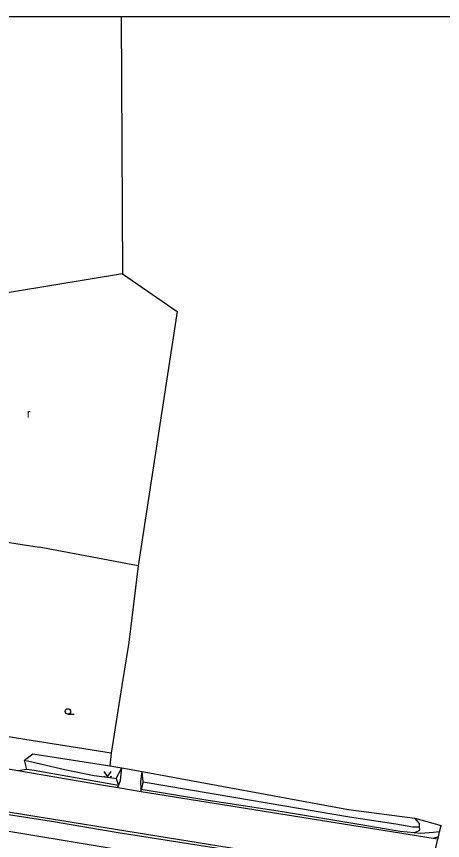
# Model space of a CAD drawing. Extents: x -591353 to -591106, y -1167325 to -1167155.
# Drawn here: x -591295 to -591237.1, y -1167266.9 to -1167154.8 of the extents above; entities that cross this region are included whole.
import ezdxf

# ---------------------------------------------------------------- set-up
doc = ezdxf.new("R2010")
doc.units = 0
for name, color, linetype in [('Level 36', 7, 'Continuous'), ('Vrstva 10', 7, 'Continuous'), ('Vrstva 11', 7, 'Continuous'), ('Vrstva 51', 7, 'Continuous'), ('Vrstva 63', 7, 'Continuous'), ('Vrstva 7', 7, 'Continuous')]:
    doc.layers.add(name, color=color, linetype=linetype)

msp = doc.modelspace()

# ---------------------------------------------------------------- linework, layer by layer
at = {"layer": 'Level 36'}
msp.add_line((-591288.05, -1167249.75), (-591287.18, -1167249.75), dxfattribs=at)
msp.add_lwpolyline([(-591283.14, -1167257.54), (-591282.64, -1167258.29), (-591282.14, -1167257.54)], dxfattribs=at)
for centre, radius in [((-591288.05, -1167249.37), 0.375), ((-591283.09, -1167258.24), 0.05), ((-591282.19, -1167258.24), 0.05)]:
    msp.add_circle(centre, radius, dxfattribs=at)
at = {"layer": 'Vrstva 10'}
for points in [[(-591294.86, -1167257.43), (-591297.72, -1167256.94)], [(-591281.26, -1167259.76), (-591282.92, -1167259.49), (-591294.86, -1167257.43)], [(-591315.62, -1167259.92), (-591254.87, -1167269.68), (-591254.39, -1167269.76), (-591239.02, -1167272.22)], [(-591278.06, -1167260.29), (-591281.26, -1167259.76)], [(-591238.35, -1167266.67), (-591278.06, -1167260.29)], [(-591237.71, -1167266.77), (-591238.35, -1167266.67)]]:
    msp.add_lwpolyline(points, dxfattribs=at)
at = {"layer": 'Vrstva 11'}
for points in [[(-591293.95, -1167255.98), (-591292.82, -1167255.12)], [(-591292.82, -1167255.12), (-591282.36, -1167256.75)], [(-591282.18, -1167255.04), (-591282.36, -1167256.75)], [(-591293.62, -1167257.29), (-591293.95, -1167255.98)], [(-591293.95, -1167255.98), (-591293.54, -1167256.08), (-591291.76, -1167256.52), (-591288.27, -1167257.3), (-591284.47, -1167258.07), (-591281.69, -1167258.44), (-591281.48, -1167258.49)], [(-591293.62, -1167257.29), (-591294.86, -1167257.43)], [(-591281.17, -1167259.46), (-591285.5, -1167258.69), (-591292.62, -1167257.41), (-591293.62, -1167257.29)], [(-591282.36, -1167256.75), (-591280.69, -1167257.06)], [(-591281.48, -1167258.49), (-591280.69, -1167257.06)], [(-591281.17, -1167259.46), (-591280.91, -1167258.78), (-591280.69, -1167257.06)], [(-591280.69, -1167257.06), (-591277.93, -1167257.56)], [(-591278.09, -1167259.97), (-591278.11, -1167258.89), (-591277.93, -1167257.56)], [(-591277.8, -1167258.94), (-591277.93, -1167257.56)], [(-591277.93, -1167257.56), (-591249.87, -1167262.71), (-591240.85, -1167263.9)], [(-591281.48, -1167258.49), (-591281.17, -1167259.46)], [(-591277.8, -1167258.94), (-591278.09, -1167259.97)], [(-591277.8, -1167258.94), (-591265.45, -1167261.03), (-591249.75, -1167263.69), (-591243.42, -1167264.68), (-591241.1, -1167265.05), (-591240.19, -1167265.08)], [(-591281.26, -1167259.76), (-591281.17, -1167259.46)], [(-591278.06, -1167260.29), (-591278.09, -1167259.97)], [(-591240.93, -1167265.89), (-591242.85, -1167265.7), (-591248.46, -1167264.77), (-591258.86, -1167263.05), (-591269.56, -1167261.38), (-591278.09, -1167259.97)], [(-591239.14, -1167272.71), (-591240.68, -1167272.27), (-591248.29, -1167271.11), (-591264.99, -1167268.44), (-591281.22, -1167265.9), (-591290.29, -1167264.35), (-591306.42, -1167261.83), (-591315.71, -1167260.43)], [(-591316.07, -1167262.37), (-591254.81, -1167272.53), (-591239.7, -1167275.04)], [(-591240.85, -1167263.9), (-591237.26, -1167264.89)], [(-591240.19, -1167265.08), (-591240.22, -1167264.61), (-591240.85, -1167263.9)], [(-591240.93, -1167265.89), (-591240.17, -1167265.54), (-591240.19, -1167265.08)], [(-591237.47, -1167265.76), (-591237.26, -1167264.89)], [(-591237.47, -1167265.76), (-591238.28, -1167265.86), (-591240.05, -1167265.97), (-591240.93, -1167265.89)], [(-591239.02, -1167272.22), (-591237.71, -1167266.77)], [(-591237.63, -1167266.45), (-591238.35, -1167266.67)], [(-591237.71, -1167266.77), (-591237.63, -1167266.45)], [(-591237.63, -1167266.45), (-591237.47, -1167265.76)]]:
    msp.add_lwpolyline(points, dxfattribs=at)
at = {"layer": 'Vrstva 51'}
msp.add_line((-591280.82, -1167154.81), (-591280.64, -1167189.82), dxfattribs=at)
for points in [[(-591280.64, -1167189.82), (-591310.05, -1167194.7)], [(-591280.64, -1167189.82), (-591273.17, -1167194.95)], [(-591273.17, -1167194.95), (-591278.51, -1167229.54)], [(-591296.6, -1167226.29), (-591291.94, -1167227.04)], [(-591278.51, -1167229.54), (-591291.94, -1167227.04)]]:
    msp.add_lwpolyline(points, dxfattribs=at)
at = {"layer": 'Vrstva 63'}
msp.add_lwpolyline([(-591352.57, -1167154.81), (-591106.03, -1167154.81), (-591106.03, -1167325.38), (-591352.57, -1167325.38)], close=True, dxfattribs=at)
at = {"layer": 'Vrstva 7'}
for points in [[(-591278.51, -1167229.54), (-591279.78, -1167240), (-591280.71, -1167245.82), (-591282.18, -1167255.04)], [(-591282.18, -1167255.04), (-591293.93, -1167253.2), (-591296.98, -1167252.69)]]:
    msp.add_lwpolyline(points, dxfattribs=at)

# ---------------------------------------------------------------- texts
at = {"layer": 'Level 36'}
msp.add_text('r', height=1.2, dxfattribs=at).set_placement((-591293.65, -1167209.41))

doc.saveas('drawing.dxf')
